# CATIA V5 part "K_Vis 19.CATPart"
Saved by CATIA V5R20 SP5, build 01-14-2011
Part number: Vis 19
Bounding box of the stored display mesh (mm): x -6 to 3, y -7 to 7, z -7 to 7
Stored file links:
  G:\Khaled_CFAO_2011\ST2M\ST2M_GR2\amorin\Khaled\CAD_Modification\K_Vis 19.CATPart
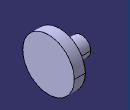
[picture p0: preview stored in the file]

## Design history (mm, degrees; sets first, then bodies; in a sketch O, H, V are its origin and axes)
Body1 (main body)
  Sketch1 on yz-plane, origin (0, 0, 0), H (0, 1, 0), V (0, 0, 1)
    circle A1 centre (0, 0) radius 7
    point P1 (7, 0)
    coincidence: A1 P1, P1 H
  Pad1: profile Sketch1, direction (1, 0, 0), length 3
  Sketch2 on yz-plane, origin (0, 0, 0), H (0, 1, 0), V (0, 0, 1)
    circle A1 centre (0, 0) radius 2.5
    point P1 (2.5, 0)
    coincidence: A1 P1, P1 H
  Pad2: profile Sketch2, direction (-1, 0, 0), length 6
  Thread1: diameter 5, depth 6, pitch 1, on face of Pad2 from Sketch2.A1, from end face of Pad2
